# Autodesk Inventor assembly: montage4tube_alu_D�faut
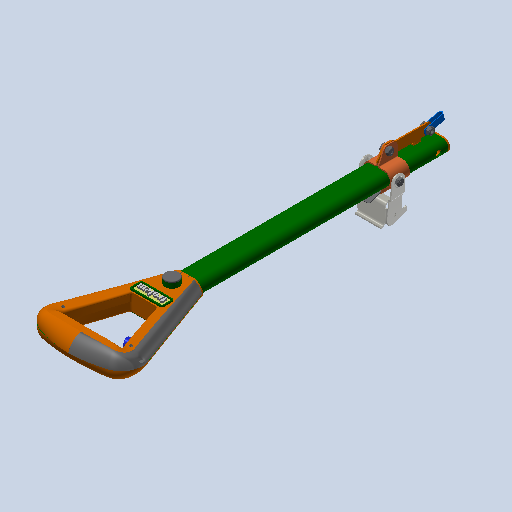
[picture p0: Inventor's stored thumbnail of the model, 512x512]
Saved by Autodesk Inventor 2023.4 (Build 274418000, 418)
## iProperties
Created: 2011-01
Part Number: montage4tube_alu_D�faut
Document SubType Name: Assembly
Designer: eric
Mass: 291.278 g
Surface Area: 2742.8 cm^2
Volume: 291.278 cm^3
Density: 1 g/cm^3
Author: eric
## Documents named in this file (18)
- C:\Users\bruno\Documents\1-Cours-2024-25\TSsI\7-Dynamique\chariot de golf\chariot_de_golf\chariot_de_golf_trolem\montage4tube_alu_Defaut.iam
- C:\Users\bruno\Documents\1-Cours-2024-25\TSsI\7-Dynamique\chariot de golf\chariot_de_golf\chariot_de_golf_trolem\46vis_a_metaux_M6_10.ipt
- C:\Users\bruno\Documents\1-Cours-2024-25\TSsI\7-Dynamique\chariot de golf\chariot_de_golf\chariot_de_golf_trolem\36Ecrou H_ FR_ M6.ipt
- C:\Users\bruno\Documents\1-Cours-2024-25\TSsI\7-Dynamique\chariot de golf\chariot_de_golf\chariot_de_golf_trolem\24poignee_femelle_Defaut.ipt
- C:\Users\bruno\Documents\1-Cours-2024-25\TSsI\7-Dynamique\chariot de golf\chariot_de_golf\chariot_de_golf_trolem\27chape_verrou_haut_Defaut.ipt
- C:\Users\bruno\Documents\1-Cours-2024-25\TSsI\7-Dynamique\chariot de golf\chariot_de_golf\chariot_de_golf_trolem\56VisChc_M8_35_Defaut.ipt
- C:\Users\bruno\Documents\1-Cours-2024-25\TSsI\7-Dynamique\chariot de golf\chariot_de_golf\chariot_de_golf_trolem\63chape_de_cable_Defaut.ipt
- C:\Users\bruno\Documents\1-Cours-2024-25\TSsI\7-Dynamique\chariot de golf\chariot_de_golf\chariot_de_golf_trolem\25_verrou_haut_Defaut.ipt
- C:\Users\bruno\Documents\1-Cours-2024-25\TSsI\7-Dynamique\chariot de golf\chariot_de_golf\chariot_de_golf_trolem\4tube_alu_Defaut.ipt
- C:\Users\bruno\Documents\1-Cours-2024-25\TSsI\7-Dynamique\chariot de golf\chariot_de_golf\chariot_de_golf_trolem\55cache_vis_Defaut.ipt
- C:\Users\bruno\Documents\1-Cours-2024-25\TSsI\7-Dynamique\chariot de golf\chariot_de_golf\chariot_de_golf_trolem\67Vis _a_ metaux_M3x25.ipt
- C:\Users\bruno\Documents\1-Cours-2024-25\TSsI\7-Dynamique\chariot de golf\chariot_de_golf\chariot_de_golf_trolem\52biellette_Defaut.ipt
- C:\Users\bruno\Documents\1-Cours-2024-25\TSsI\7-Dynamique\chariot de golf\chariot_de_golf\chariot_de_golf_trolem\24poignee_male_Defaut.ipt
- C:\Users\bruno\Documents\1-Cours-2024-25\TSsI\7-Dynamique\chariot de golf\chariot_de_golf\chariot_de_golf_trolem\75commande_Defaut.ipt
- C:\Users\bruno\Documents\1-Cours-2024-25\TSsI\7-Dynamique\chariot de golf\chariot_de_golf\chariot_de_golf_trolem\35Vis_CBLZ_M6_55.ipt
- C:\Users\bruno\Documents\1-Cours-2024-25\TSsI\7-Dynamique\chariot de golf\chariot_de_golf\chariot_de_golf_trolem\58embout_ovale_Defaut.ipt
- C:\Users\bruno\Documents\1-Cours-2024-25\TSsI\7-Dynamique\chariot de golf\chariot_de_golf\chariot_de_golf_trolem\26ressort_verrou_haut_Defaut.ipt
- C:\Users\bruno\Documents\1-Cours-2024-25\TSsI\7-Dynamique\chariot de golf\chariot_de_golf\chariot_de_golf_trolem\66rivet_Defaut.ipt
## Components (23 placed, 17 different names)
1. 46vis_a_metaux_M6_10:1
2. 36Ecrou H_ FR_ M6:1
3. 24poignee_femelle_Defaut:1
4. 27chape_verrou_haut_Defaut:1
5. 56VisChc_M8_35_Defaut:1
6. 63chape_de_cable_Defaut:1
7. 25_verrou_haut_Defaut:1
8. 4tube_alu_Defaut:1
9. 55cache_vis_Defaut:1
10. 67Vis _a_ metaux_M3x25:1
11. 52biellette_Defaut:1
12. 55cache_vis_Defaut:2
13. 67Vis _a_ metaux_M3x25:2
14. 36Ecrou H_ FR_ M6:2
15. 36Ecrou H_ FR_ M6:3
16. 46vis_a_metaux_M6_10:2
17. 24poignee_male_Defaut:1
18. 75commande_Defaut:1
19. 36Ecrou H_ FR_ M6:4
20. 35Vis_CBLZ_M6_55:1
21. 58embout_ovale_Defaut:1
22. 26ressort_verrou_haut_Defaut:1
23. 66rivet_Defaut:1
